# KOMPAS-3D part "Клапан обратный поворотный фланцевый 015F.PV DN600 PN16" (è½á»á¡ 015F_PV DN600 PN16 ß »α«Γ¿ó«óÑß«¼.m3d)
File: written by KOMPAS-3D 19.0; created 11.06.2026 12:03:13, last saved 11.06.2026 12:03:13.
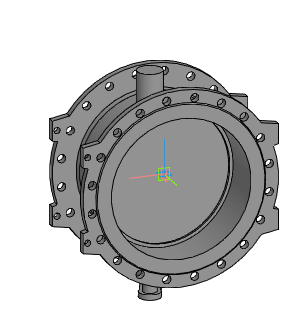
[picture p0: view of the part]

Document properties: Автор: Энергия; Полное имя файла: Z:\3.Личные\kachalov\001_3d для проектировщиков\5.5 Тип 015F.PV Клапан обратный поворотный с двумя эксцентриками\_stp_Клапан 015F.PV DN300-DN1200 с противовесом\Клапан 015F_PV DN600 PN16 с противовесом.m3d

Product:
- Part/product: Клапан обратный поворотный фланцевый 015F.PV DN600 PN16

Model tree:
1. Операция без истории:1
2. Сплайн:1
     Координата Y = 30; Координата Z = 300; Вес = 1; Координата X = 600; Координата Y = 108.991; Координата Z = 300; Вес = 0.333333; Координата X = 600; Координата Y = 108.991; Координата Z = -300; Вес = 0.333333; Координата Y = 30; Координата Z = -300; Вес = 1; Координата X = -600; Координата Y = -48.9915; Координата Z = -300; Вес = 0.333333; Координата X = -600; Координата Y = -48.9915; Координата Z = 300; Вес = 0.333333; Порядок = 4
